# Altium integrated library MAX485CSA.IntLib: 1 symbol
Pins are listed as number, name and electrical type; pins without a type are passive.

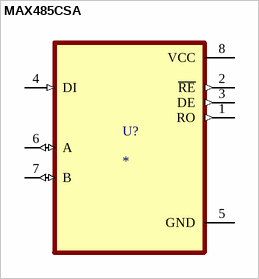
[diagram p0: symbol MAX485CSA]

## MAX485CSA
designator U?
MP: MAX485CSA
footprint SOIC127P600X175-8N
pins: 1 RO (out), 2 ~{RE} (out), 3 DE (out), 4 DI (in), 5 GND (power), 6 A (io), 7 B (io), 8 VCC (power)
